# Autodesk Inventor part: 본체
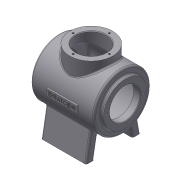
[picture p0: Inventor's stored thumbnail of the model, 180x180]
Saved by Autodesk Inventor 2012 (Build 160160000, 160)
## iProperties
Created: 2015-01
Part Number: 본체
Material: 알루미늄-6061
Document SubType Name: Modeling
Designer: Class3-User
Mass: 1021.16 g
Surface Area: 1060.1 cm^2
Volume: 376.81 cm^3
Density: 2.71 g/cm^3
Author: Class3-User
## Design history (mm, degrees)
sketch "스케치2"
  geometry: C1 r 50 at (0, 0); 1 further point
  constraints: 1 centre point, 1 coincident
  dimensions: "d0" = 100 diameter of C1
extrude "돌출1" new body sketch "스케치2" stored distance "d1" = 112; taper "d3" = 0 deg; dims "d2" = 57, "d4" = 0
sketch "스케치3"
  geometry: L1 (-39.336, -30.865)-(-48, -80); L2 (-48, -80)-(-34, -80); L3 (-34, -80)-(-27.282, -41.901); L4 (0, 0)-(0, -50); A1 r 50 centre (0, 0) between (-27.282, -41.901) and (-39.336, -30.865) reference; 1 further point
  constraints: 8 end point, 3 point on circle, 1 horizontal, 1 parallel, 1 perpendicular
  dimensions: "d5" = 96 diameter of L1.end L4; "d6" = 10 deg angle of L4 L3; "d7" = 14 distance of L1.end L2.end; "d8" = 80 distance from line of L2 point (0, 0)
extrude "돌출2" join sketch "스케치3" stored distance "d9" = 80; taper "d10" = 0 deg
sketch "스케치4"
  geometry: L1 (56, 50)-(56, -50) reference; C1 r 38 at (1, 0); 1 further point
  constraints: 1 centre point, 1 horizontal alignment
  dimensions: "d14" = 76 diameter of C1; "d15" = 55 distance from line of L1 C1.centre
extrude "돌출3" join sketch "스케치4" distance "d16" = 62; taper "d17" = 0 deg
sketch "스케치5"
  geometry: C1 r 50 at (0, 0) reference; C2 r 38 at (0, 0)
  constraints: 1 centre point, 1 coincident
  dimensions: "d18" = 76 diameter of C2
extrude "돌출4" join sketch "스케치5" distance "d19" = 5; taper "d20" = 0 deg
sketch "스케치7"
  geometry: L1 (0, 45)-(0, 0); L2 (56, 50)-(56, -50) reference; L3 (-49, 0)-(-49, 45); L4 (-49, 45)-(48, 45); L5 (48, 45)-(48, 0); L6 (-49, 0)-(48, 0); L7 (85.4, 0)-(-85.4, 0) reference; 1 further point
  constraints: 10 end point, 2 perpendicular, 2 vertical, 1 midpoint, 1 parallel, 1 point on line
  dimensions: "d91" = 97 distance of L3.start L5.end; "d93" = 8 distance between parallel lines of L2 L5; "d94" = 90 diameter of L4 L6
revolve "회전1" sketch "스케치7" stored, may be unused: angle "d25" = 90 deg
hole "구멍1" diameter "d28" = 54; stored, may be unused: countersink angle "d32" = 90 deg, drill point angle "d34" = 118 deg; dims "d26" = 10, "d27" = 10, "d29" = 6, "d30" = 4, "d31" = 2, "d33" = 8
hole "구멍2" diameter "d37" = 54; stored, may be unused: countersink angle "d41" = 90 deg, drill point angle "d43" = 118 deg; dims "d38" = 6, "d39" = 4, "d40" = 2, "d42" = 8, "d95" = 10, "d96" = 10
sketch "스케치8"
  geometry: C1 r 27 at (0, 0) reference; 1 further point
  constraints: 1 horizontal alignment
  dimensions: "d52" = 32 distance of point (-32, 0) C1.centre
hole "구멍3" sketch "스케치8" at (-32, 0) diameter "d45" = 3.242; stored, may be unused: countersink angle "d49" = 90 deg, drill point angle "d51" = 118 deg; dims "d46" = 8, "d47" = 4, "d48" = 2, "d50" = 10
sketch "스케치9"
  geometry: C1 r 1.621 at (32, 0) reference
hole "구멍4" sketch "스케치9" at (32, 0) diameter "d56" = 3.242; stored, may be unused: countersink angle "d60" = 90 deg, drill point angle "d62" = 118 deg; dims "d57" = 8, "d58" = 4, "d59" = 2, "d61" = 10
fillet "모깎기2" dims "d67" = 3
fillet "모깎기1" dims "d66" = 3
sketch "스케치10"
  geometry: C1 r 27 at (0, 0) reference; 2 further points
  constraints: 1 vertical alignment
  dimensions: "d68" = 32 distance of C1.centre point (0, 32)
hole "구멍5" sketch "스케치10" at (0, 32) diameter "d69" = 3.242; stored, may be unused: countersink angle "d73" = 90 deg, drill point angle "d75" = 118 deg; dims "d70" = 8, "d71" = 4, "d72" = 2, "d74" = 10
node "작업 평면2"
sketch "스케치11"
  geometry: L1 (-26, 6)-(28, 6); L2 (28, 6)-(28, -6); L3 (28, -6)-(-26, -6); L4 (-26, -6)-(-26, 6); L5 (61, 38)-(61, -38) reference; 3 further points
  constraints: 8 end point, 2 midpoint, 2 parallel, 1 horizontal, 1 horizontal alignment, 1 perpendicular
  dimensions: "d97" = 54 distance of L1.start L1.end; "d98" = 12 distance of L3.end L1.start; "d99" = 60 distance from line of L5 point (1, 6)
extrude "돌출5" join sketch "스케치11" stored distance "d82" = 5; taper "d83" = 0 deg
sketch "스케치12"
  geometry: L1 (-26, 6)-(28, 6) reference; L2 (28, 6)-(28, -6) reference; 5 further points
  constraints: 3 midpoint, 1 coincident, 1 horizontal alignment, 1 vertical alignment, 1 other
feature "엠보싱1" sketch "스케치12" dims "d84" = 0.5, "d85" = 0
chamfer "모따기1" distance "d86" = 1; stored, may be unused: second distance "d87" = 2, angle "d88" = 45 deg
node "솔리드1"
mirror "대칭1"
mirror "대칭2"
pattern_circular "원형 패턴1" dims angle "d54" = 360 deg
pattern_circular "원형 패턴2" dims angle "d64" = 360 deg
pattern_circular "원형 패턴3" dims angle "d77" = 360 deg
other parameters: "d79" = -52
